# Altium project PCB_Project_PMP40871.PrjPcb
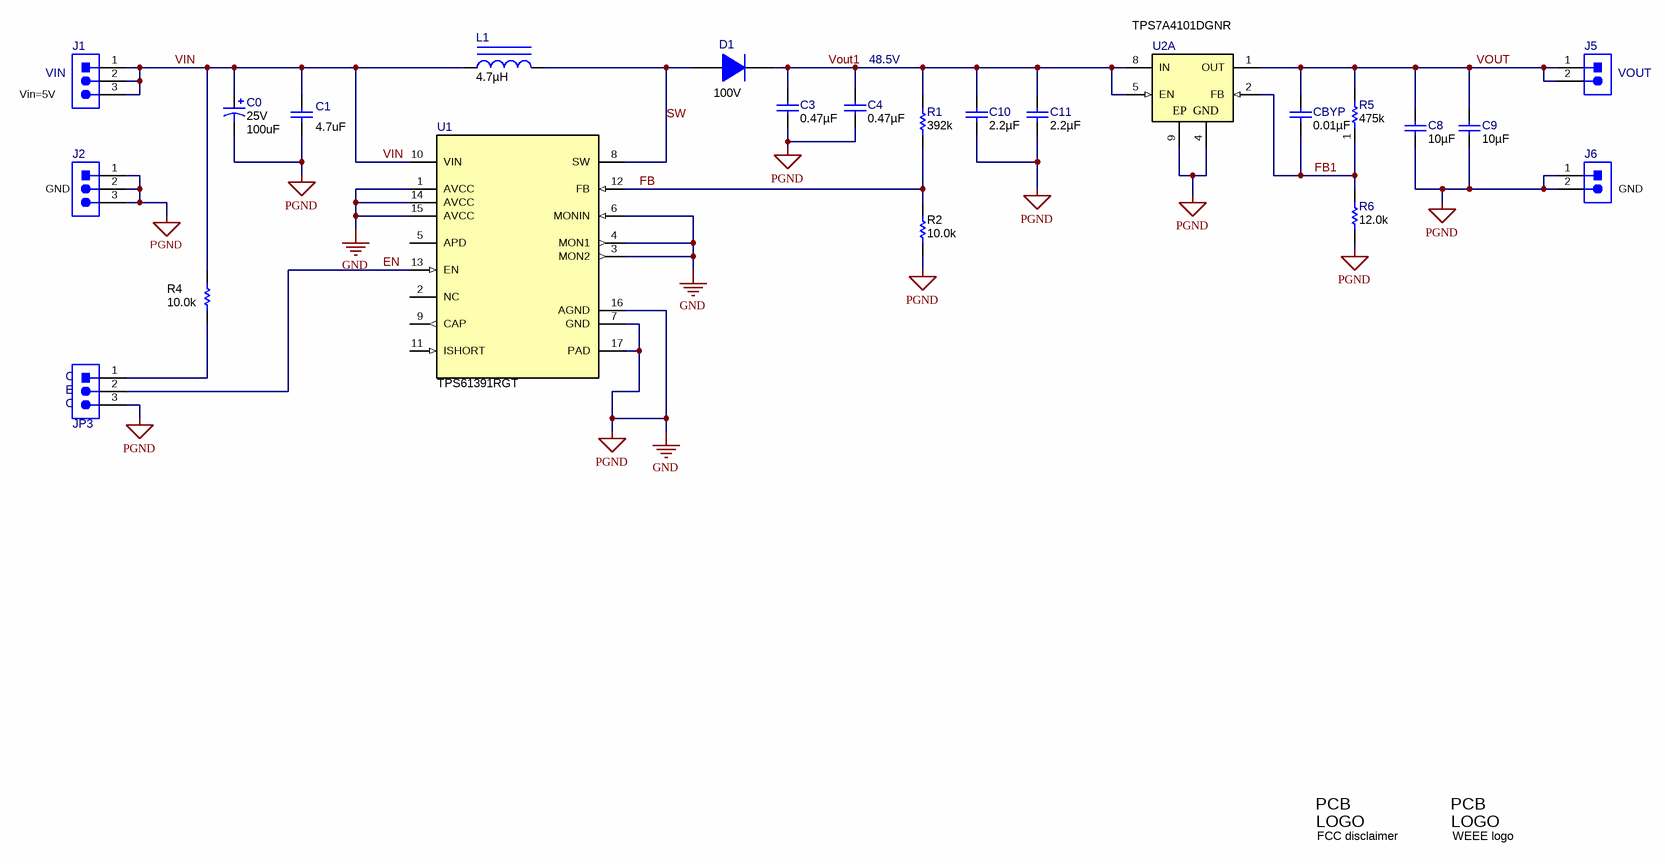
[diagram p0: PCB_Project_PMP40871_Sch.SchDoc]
CopyrightYear: 2018; PCB_Layout: Who did the Layout?; PCB_Rev: E1; PRJ_Customer: Public Release; PRJ_Engineer: Enter name of project lead; PRJ_Number: XX####; PRJ_Title: Change in menu Project|Project Options|Parameters; SCH_Rev: E1; TechSupport: http://www.ti.com/support; TID: N/A
1 sheet, 25 parts. Net scope: global (net labels, ports and power ports of the same name join across sheets).
Board file: PCB_Project_PMP40871_PCB.PcbDoc

## Sheet PCB_Project_PMP40871_Sch.SchDoc: TPS61391EVM-058
size A3; Date: Not shown in title block; ApprovedBy: Not shown in title block; CheckedBy: Not shown in title block; Author: Not shown in title block; CompanyName: Not shown in title block; DrawnBy: Helen Chen; Engineer: Not shown in title block; Organization: Not shown in title block; Address1: Not shown in title block; Address2: Not shown in title block; Address3: Not shown in title block; Address4: Not shown in title block; DocumentNumber: 1; Revision: Use project parameter SCH_Rev; SheetNumber: 1; SheetTotal: 2; PageSetup: Record=PageOptions¦CenterHorizontal=True¦CenterVertical=True¦PrintScale=1.00¦XCorrection=1.00¦YCorrection=1.00¦PrintKind=0¦BorderSize=5000000¦LeftOffset=0¦BottomOffset=0¦Orientation=2¦PaperLength=1000¦PaperWidth=1000¦Scale=100¦PaperSource=15¦PrintQuality=600¦MediaType=1¦DitherType=10¦PaperKind=Letter¦PrintScaleMode=1

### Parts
C0  VDC_V: 25V  ValueDisplayed: 100uF  [SM_RADIAL_6.3BMM]  (hidden comment: EEHZA1E101XP)
C1  ValueDisplayed: 4.7uF  [0603]  (hidden comment: GRM188R61C475KAAJ)
C3  ValueDisplayed: 0.47µF  [0805_HV]  (hidden comment: C2012X7S2A474K125AB)
C4  ValueDisplayed: 0.47µF  [0805_HV]  (hidden comment: C2012X7S2A474K125AB)
C8  ValueDisplayed: 10µF  [1206_190]  (hidden comment: CGA5L1X7R1H106K160AC)
C9  ValueDisplayed: 10µF  [1206_190]  (hidden comment: CGA5L1X7R1H106K160AC)
C10  ValueDisplayed: 2.2µF  [1206_180]  (hidden comment: CGA5L3X7S2A225K160AB)
C11  ValueDisplayed: 2.2µF  [1206_180]  (hidden comment: CGA5L3X7S2A225K160AB)
CBYP  ValueDisplayed: 0.01µF  [0603]  (hidden comment: C0603C103J1RACTU)
D1  value 100V  [SOD-123]  (hidden comment: BAS16D-E3-08)
J1  Header_3x1_Launchpad  [CONN_PEC03SAAN]  (value not drawn)
J2  Header_3x1_Launchpad  [CONN_PEC03SAAN]  (value not drawn)
J5  Header_2x1  [CONN_PEC02SAAN]  (value not drawn)
J6  Header_2x1  [CONN_PEC02SAAN]  (value not drawn)
JP3  Header_3x1_Launchpad  [CONN_PEC03SAAN]  (value not drawn)
L1  ValueDisplayed: 4.7µH  [DFE201612E]  (hidden comment: DFE201612E-4R7M=P2)
Logo1  FCC disclaimer  [FCC_disclaimer]  (no BOM)
Logo2  WEEE logo  [WEEE_Minimum]  (no BOM)
R1  ValueDisplayed: 392k  [0603]  (hidden comment: RT0603BRD07392KL)
R2  ValueDisplayed: 10.0k  [0603]  (hidden comment: Resistor)
R4  ValueDisplayed: 10.0k  [0603]  (hidden comment: Resistor)
R5  ValueDisplayed: 475k  [0603]  (hidden comment: RC0603FR-07475KL)
R6  ValueDisplayed: 12.0k  [0603]  (hidden comment: RC0603FR-0712KL)
U1  TPS61391RGT  [RGT0016C]
U2  TPS7A4101DGNR  [DGN0008B_N]  (part A of 2)

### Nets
GND: C0.2(-) C1.2 C3.2 C4.2 C8.2 C9.2 C10.2 C11.2 J2.1 J2.2 J2.3 J6.1 J6.2 JP3.3 R2.1 R6.1 U1.1(AVCC) U1.3(MON2) U1.4(MON1) U1.6(MONIN) U1.7(GND) U1.14(AVCC) U1.15(AVCC) U1.16(AGND) U1.17(PAD) U2.4(GND) U2.9(EP)  [also labelled PGND]
EN: JP3.2 U1.13(EN)
FB: R1.1 R2.2 U1.12(FB)
FB1: CBYP.2 R5.1 R6.2 U2.2(FB)
SW: D1.2(A) L1.2 U1.8(SW)
VIN: C0.1(+) C1.1 J1.1 J1.2 J1.3 L1.1 R4.2 U1.10(VIN)
VOUT: C8.1 C9.1 CBYP.1 J5.1 J5.2 R5.2 U2.1(OUT)
Vout1: C3.1 C4.1 C10.1 C11.1 D1.1(K) R1.2 U2.5(EN) U2.8(IN)
NetJP3_1: JP3.1 R4.1

Not connected (* = marked no-connect by the designer): U1 2(NC) 5(APD) 9(CAP) 11(ISHORT)

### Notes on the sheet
- (near J1) VIN
- 48.5V
- (near J5) VOUT
- (near J1) Vin=5V
- (near J2) GND
- (near J6) GND
- (near JP3) EN
- (near JP3) ON
- (near JP3) OFF

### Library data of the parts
C0 = CMP-0012570-3: CAP, Polymer Hybrid, 100 uF, 25 V, +/- 20%, 30 ohm, 6.3x7.7 SMD; Manufacturer: Panasonic; TaMin_C: -55°C; ESR_ohm: 30; Polarized: Y; SizeAreaWB_mm2: 79.98; Value1: 30 ohm; Value: 100uF; TaMax_C: 105°C; SizeZ_mm: 7.7; SizeX_mm: 7.3; SizeY_mm: 6.6; SizeArea_mm2: 48.18; CompType: Capacitor; Cap_F: 100µF; IRMS_A: 2A; AEC Category: Q200
C1 = CMP-0007341-5: CAP, CERM, 4.7 uF, 16 V, +/- 10%, X5R, 0603; Manufacturer: MuRata; TaMin_C: -55°C; Polarized: N; SizeAreaWB_mm2: 4.68; Value1: Unknown; U/M: EA; Value: 4.7uF; TaMax_C: 85°C; SizeZ_mm: 1; SizeX_mm: 1.6; SizeY_mm: 0.8; Value2: 16V; SizeArea_mm2: 1.28; CompType: Capacitor; Cap_F: 4.7µF; AEC Category: Q200
C3 C4 = C2012X7S2A474K125AB: CAP, CERM, 0.47 µF, 100 V,+/- 10%, X7S, 0805; Manufacturer: TDK; Polarized: N; CompType: Capacitor; Value: 0.47uF; U/M: EA; Cap_F: 0.00000047; Tolerance_%: 10; ESR_ohm: 0.017152; Value1: 0.017152 ohm; VDC_V: 100; Value2: 100V; IRMS_A: 1.58068; TaMin_C: -55; TaMax_C: 125; Cap_Case: 0805; SizeArea_mm2: 2.5; SizeAreaWB_mm2: 6.75; SizeX_mm: 2; SizeY_mm: 1.25; SizeZ_mm: 1.45; AEC Category: Q200
C8 C9 = CMP-0085950-1: CAP, CERM, 10 µF, 50 V,+/- 10%, X7R, AEC-Q200 Grade 1, 1206; Manufacturer: TDK; SizeZ_mm: 1.9; Value: 10uF; Value2: 50V; Cap_Case: 1206; AEC Grade: 1; TaMin_C: -55°C; U/M: EA; CompType: Capacitor; SizeArea_mm2: 5.12; TaMax_C: 125°C; AEC Qualified: Y; AEC Category: Q200; SizeX_mm: 3.2; SizeY_mm: 1.6; Polarized: N; SizeAreaWB_mm2: 10.92
C10 C11 = CGA5L3X7S2A225K160AB: CAP, CERM, 2.2 µF, 100 V,+/- 10%, X7S, AEC-Q200 Grade 1, 1206; Manufacturer: TDK; Polarized: N; CompType: Capacitor; Value: 2.2uF; U/M: EA; Cap_F: 0.0000022; Tolerance_%: 10; ESR_ohm: 0.005718; Value1: 0.005718 ohm; VDC_V: 100; Value2: 100V; IRMS_A: 3.03632; TaMin_C: -55; TaMax_C: 125; Cap_Case: 1206; SizeArea_mm2: 5.12; SizeAreaWB_mm2: 10.92; SizeX_mm: 3.2; SizeY_mm: 1.6; SizeZ_mm: 1.8; AEC Category: Q200; AEC Qualified: Y; AEC Grade: 1
CBYP = C0603C103J1RACTU: CAP, CERM, 0.01 µF, 100 V,+/- 5%, X7R, 0603; Manufacturer: Kemet; Polarized: N; CompType: Capacitor; Value: 0.01uF; U/M: EA; Cap_F: 0.00000001; Tolerance_%: 5; VDC_V: 100; Value2: 100V; TaMin_C: -55; TaMax_C: 125; SizeArea_mm2: 1.28; SizeAreaWB_mm2: 4.68; SizeX_mm: 1.6; SizeY_mm: 0.8; SizeZ_mm: 1; AEC Category: Q200; Green_Lifecycle: Active; Green_REACh: Passed
D1 = CMP-0080761-1: Diode, Switching, 100 V, 0.25 A, AEC-Q101, SOD-123; Manufacturer: Vishay-Semiconductor; Io_A: 2.5dA; SizeAreaWB_mm2: 13.095; Value1: 0.25A; TJmax_C: 150°C; SizeZ_mm: 1.35; SizeX_mm: 3.85; SizeY_mm: 1.7; Vf_V: 1.25V; SizeArea_mm2: 6.545; AEC Qualified: Y; AEC Category: Q101
J1 J2 JP3 = CMP-0002338-1: Header, 100mil, 3x1, Tin, TH; PartNumber: PEC03SAAN; Manufacturer: Sullins Connector Solutions; Pitch_mm: 2.54; Gender: Male; Shrouded: N; Row_Count: 1; Current_A: 3A; Voltage_V: 1.8kV; Cert_UL: Y; Green_Lifecycle: Not Set; Green_REACh: Incomplete; CNHeader: TRUE; CT: FALSE
J5 J6 = CMP-0002337-1: Header, 100mil, 2x1, Tin, TH; PartNumber: PEC02SAAN; Manufacturer: Sullins Connector Solutions; Pitch_mm: 2.54; Gender: Male; Shrouded: N; Row_Count: 1; Current_A: 3A; Voltage_V: 1.8kV; Cert_UL: Y; Green_Lifecycle: Not Set; Green_REACh: Incomplete; CNHeader: TRUE; CT: FALSE
L1 = CMP-0080776-1: Inductor, Shielded, Metal Composite, 4.7 µH, 1.2 A, 0.252 ohm, SMD; Manufacturer: MuRata; Isat: 1.8A @ 30% inductance drop; Irms: 1.2A @ 40C rise; SizeAreaWB_mm2: 7.8; DCR_ohm: 2.52d; Value: 4.7uH; Imax_A: 1.2A; SizeZ_mm: 1.2; SizeX_mm: 2; SizeY_mm: 1.6; SizeArea_mm2: 3.2; AEC Qualified: N; AEC Category: Q200
Logo1 = CMP-0074847-1: FCC_disclaimer; Library Reference: Logo
Logo2 = CMP-0074769-1
R1 = RT0603BRD07392KL: RES, 392 k, 0.1%, 0.1 W, 0603; Manufacturer: Yageo America; CompType: Resistor; Value: 392k; Res_ohm: 392000; Tolerance_%: 0.1; Value2: 0.1W; VDC_V: 75; TempCo: 25 ppm/C; SizeArea_mm2: 1.28; SizeX_mm: 1.6; SizeY_mm: 0.8; SizeZ_mm: 1; EIA_Code: E192; U/M: EA; AEC Category: Q200
R2 R4 = CMP-0021998-4: RES, 10.0 k, 1%, 0.1 W, AEC-Q200 Grade 0, 0603; PartNumber: CRCW060310K0FKEA; Manufacturer: Vishay-Dale; Value: 10.0k; Res_ohm: 10k; Value_Code: 10k0; Power_W: 100mW; Value2: 0.1W; VDC_V: 75V; TempCo: 100 ppm/C; SizeArea_mm2: 1.28; SizeX_mm: 1.6; SizeY_mm: 0.8; SizeZ_mm: 1; EIA_Code: E96; AEC Category: Q200; AEC Qualified: Y; AEC Grade: 0
R5 = CMP-0023130-4: RES, 475 k, 1%, 0.1 W, 0603; Manufacturer: Yageo; Power_W: 100mW; TempCo: 100 ppm/C; Value: 475k; EIA_Code: E96; SizeX_mm: 1.6; SizeY_mm: 0.8; SizeZ_mm: 1; Value2: 0.1W; SizeArea_mm2: 1.28; CompType: Resistor; AEC Qualified: N; VDC_V: 75V; AEC Category: Q200; SizeAreaWB_mm2: 4.68
R6 = CMP-0022779-5: RES, 12.0 k, 1%, 0.1 W, 0603; Manufacturer: Yageo; Power_W: 100mW; TempCo: 100 ppm/C; Value_Code: 12k0; Value: 12.0k; Res_ohm: 12k; SizeX_mm: 1.6; SizeY_mm: 0.8; SizeZ_mm: 1; Value2: 0.1W; SizeArea_mm2: 1.28; AEC Qualified: N; VDC_V: 75V; AEC Category: Q200; SizeAreaWB_mm2: 4.68
U1 = CMP-0860736-1: 85-VOUT Boost Converter with Current Mirror and Sample / Hold, RGT0016C (VQFN-16); Alternate Manufacturer: Texas Instruments; SizeZ_mm: 1; CompType: IC; SizeArea_mm2: 9; SizeX_mm: 3; AEC Category: Q200; SizeAreaWB_mm2: 16; AEC Qualified: N
U2 = TPS7A4101DGNR: Single Output LDO, 50 mA, Adjustable 1.175 to 48 V Output, 7 to 50 V Input, 8-pin MSOP (DGN), -40 to 125 degC, Green (RoHS & no Sb/Br); Manufacturer: Texas Instruments; Alternate PartNumber: Equivalent; Accuracy(%): 1; Iout(Max)(A): 0.05; Iq(Typ)(mA): 0.02; SubFamily: Single Channel LDO; Vdo(Typ)(mV): 290; Vin(Max)(V): 50; Vin(Min)(V): 7; Vout Adj(Max)(V): 48; Vout Adj(Min)(V): 1.161

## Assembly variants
001: not fitted FID1 FID2 FID3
